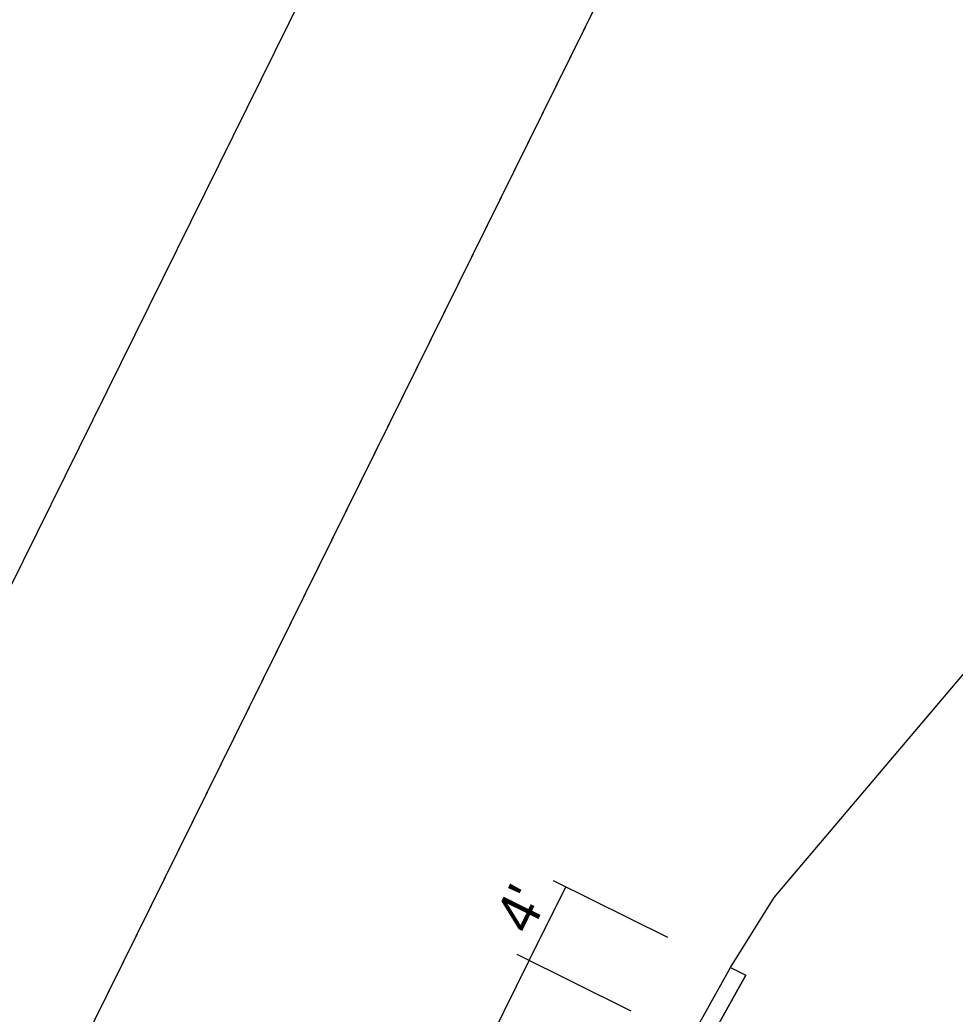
# Model space of a CAD drawing. Extents: x 14104283 to 14128447, y 8633203 to 8671666.
# Drawn here: x 14118461.5 to 14118643.5, y 8668631.4 to 8668824.8 of the extents above; entities that cross this region are included whole.
import ezdxf

# ---------------------------------------------------------------- set-up
doc = ezdxf.new("R2010")
doc.units = 0
for name, color, linetype in [('dsnNonPlotable', 7, 'Continuous'), ('dsnStgShadingPrevPav', 7, 'Continuous'), ('dsnTextFinalPlan', 7, 'Continuous'), ('dsnTextOverlapEven', 7, 'Continuous'), ('TC_SubstrataExistingPavement', 7, 'Continuous'), ('Terrain', 7, 'Continuous')]:
    doc.layers.add(name, color=color, linetype=linetype)

msp = doc.modelspace()

# ---------------------------------------------------------------- linework, layer by layer
at = {"layer": 'dsnNonPlotable'}
msp.add_lwpolyline([(14118092.03, 8667853.71), (14118786.76, 8669258.84), (14119692.14, 8668811.2), (14118997.41, 8667406.07)], close=True, dxfattribs=at)
at = {"layer": 'dsnStgShadingPrevPav'}
msp.add_lwpolyline([(14118591.93, 8668626.39), (14118599.79, 8668640.48), (14118602.77, 8668639), (14118594.92, 8668624.92)], close=True, dxfattribs=at)
at = {"layer": 'dsnTextFinalPlan'}
for p, q in [((14118560.65, 8668641.86), (14118567.74, 8668656.2)), ((14118565.29, 8668657.42), (14118587.52, 8668646.42)), ((14118558.2, 8668643.07), (14118580.43, 8668632.08)), ((14118539.37, 8668598.83), (14118560.65, 8668641.86))]:
    msp.add_line(p, q, dxfattribs=at)
for points in [[(14117870.36, 8667977.42), (14118384.92, 8669018.16), (14118565.56, 8668928.85), (14118050.99, 8667888.12)], [(14118092.03, 8667853.71), (14118606.59, 8668894.44), (14118787.23, 8668805.14), (14118272.66, 8667764.4)]]:
    msp.add_lwpolyline(points, close=True, dxfattribs=at)
at = {"layer": 'dsnTextOverlapEven'}
msp.add_lwpolyline([(14117870.36, 8667977.42), (14118384.92, 8669018.16), (14118565.56, 8668928.85), (14118050.99, 8667888.12)], close=True, dxfattribs=at)
at = {"layer": 'TC_SubstrataExistingPavement'}
msp.add_line((14118599.79, 8668640.48), (14118602.77, 8668639), dxfattribs=at)
msp.add_lwpolyline([(14118559.8, 8668561.96), (14118576.44, 8668591.8), (14118583.24, 8668603.98), (14118602.77, 8668639)], dxfattribs=at)
at = {"layer": 'Terrain'}
for points in [[(14118599.79, 8668640.48), (14118608.32, 8668654.13), (14118654.78, 8668708.88), (14118678.97, 8668737.39), (14118696.75, 8668773.34), (14118700.24, 8668798.42), (14118703.85, 8668824.42)], [(14118556.81, 8668563.44), (14118573.45, 8668593.27), (14118580.25, 8668605.46), (14118599.79, 8668640.48)]]:
    msp.add_lwpolyline(points, dxfattribs=at)

# ---------------------------------------------------------------- texts
at = {"layer": 'dsnTextFinalPlan'}
msp.add_text("4'", height=8, rotation=63.6911, dxfattribs=at).set_placement((14118560.78, 8668646.59))

doc.saveas('drawing.dxf')
